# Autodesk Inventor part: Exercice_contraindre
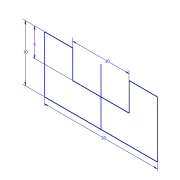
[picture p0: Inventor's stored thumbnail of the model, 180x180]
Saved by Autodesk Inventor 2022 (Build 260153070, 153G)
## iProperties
Created: 2021-05
Part Number: Exercice_contraindre
Material: Générique
Document SubType Name: Modeling
Designer: Fabian
Density: 1 g/cm^3
Appearance: Par défaut
Author: Fabian
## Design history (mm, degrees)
sketch "Esquisse1"
  geometry: L1 (0, 0)-(0, 10); L2 (5, 10)-(10, 10); L3 (10, 10)-(10, 0); L4 (10, 0)-(-10, 0); L5 (-10, 0)-(-10, 10); L6 (-10, 10)-(-5, 10); L7 (-5, 10)-(-5, 5); L8 (-5, 5)-(5, 5); L9 (5, 5)-(5, 10)
  constraints: 18 end point, 5 perpendicular, 2 point on line, 2 vertical, 1 horizontal, 1 horizontal alignment, 1 midpoint, 1 other
  dimensions: "d4" = 10 distance of L4.end L5.end; "d5" = 5 distance of L6.end L7.end; "d6" = 20 distance of L3.end L4.end; "d7" = 10 distance of L7.end L8.end
